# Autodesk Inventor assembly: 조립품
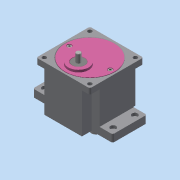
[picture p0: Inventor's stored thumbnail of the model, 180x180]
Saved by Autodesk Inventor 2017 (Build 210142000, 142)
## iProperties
Part Number: 조립품
Material: 일반
Document SubType Name: Assembly
Designer: user
Author: user
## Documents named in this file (10)
- C:\Users\user\Desktop\700116V1011\조립품.iam
- C:\Users\user\Desktop\700116V1011\베어링 608.ipt
- C:\Users\user\Desktop\700116V1011\베어링 6003.ipt
- C:\Users\user\Desktop\700116V1011\본체.ipt
- C:\Users\user\Desktop\700116V1011\볼트 M4.ipt
- C:\Users\user\Desktop\700116V1011\서브 축.ipt
- C:\Users\user\Desktop\700116V1011\오일 실 8 22 7.ipt
- C:\Users\user\Desktop\700116V1011\오일 실 17 32 8.ipt
- C:\Users\user\Desktop\700116V1011\커버.ipt
- C:\Users\user\Desktop\700116V1011\메인 축.ipt
